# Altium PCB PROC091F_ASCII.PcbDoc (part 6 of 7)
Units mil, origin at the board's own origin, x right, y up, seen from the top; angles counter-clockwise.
Board outline 3590.95 x 906.17 mil, 8 copper layers (Top Layer, GND1, Sig1, PWR1, PWR2, Sig2, GND2, Bottom Layer), stack 63.146 mil thick; 420 components, 316 nets, 1432 pads, 774 vias.
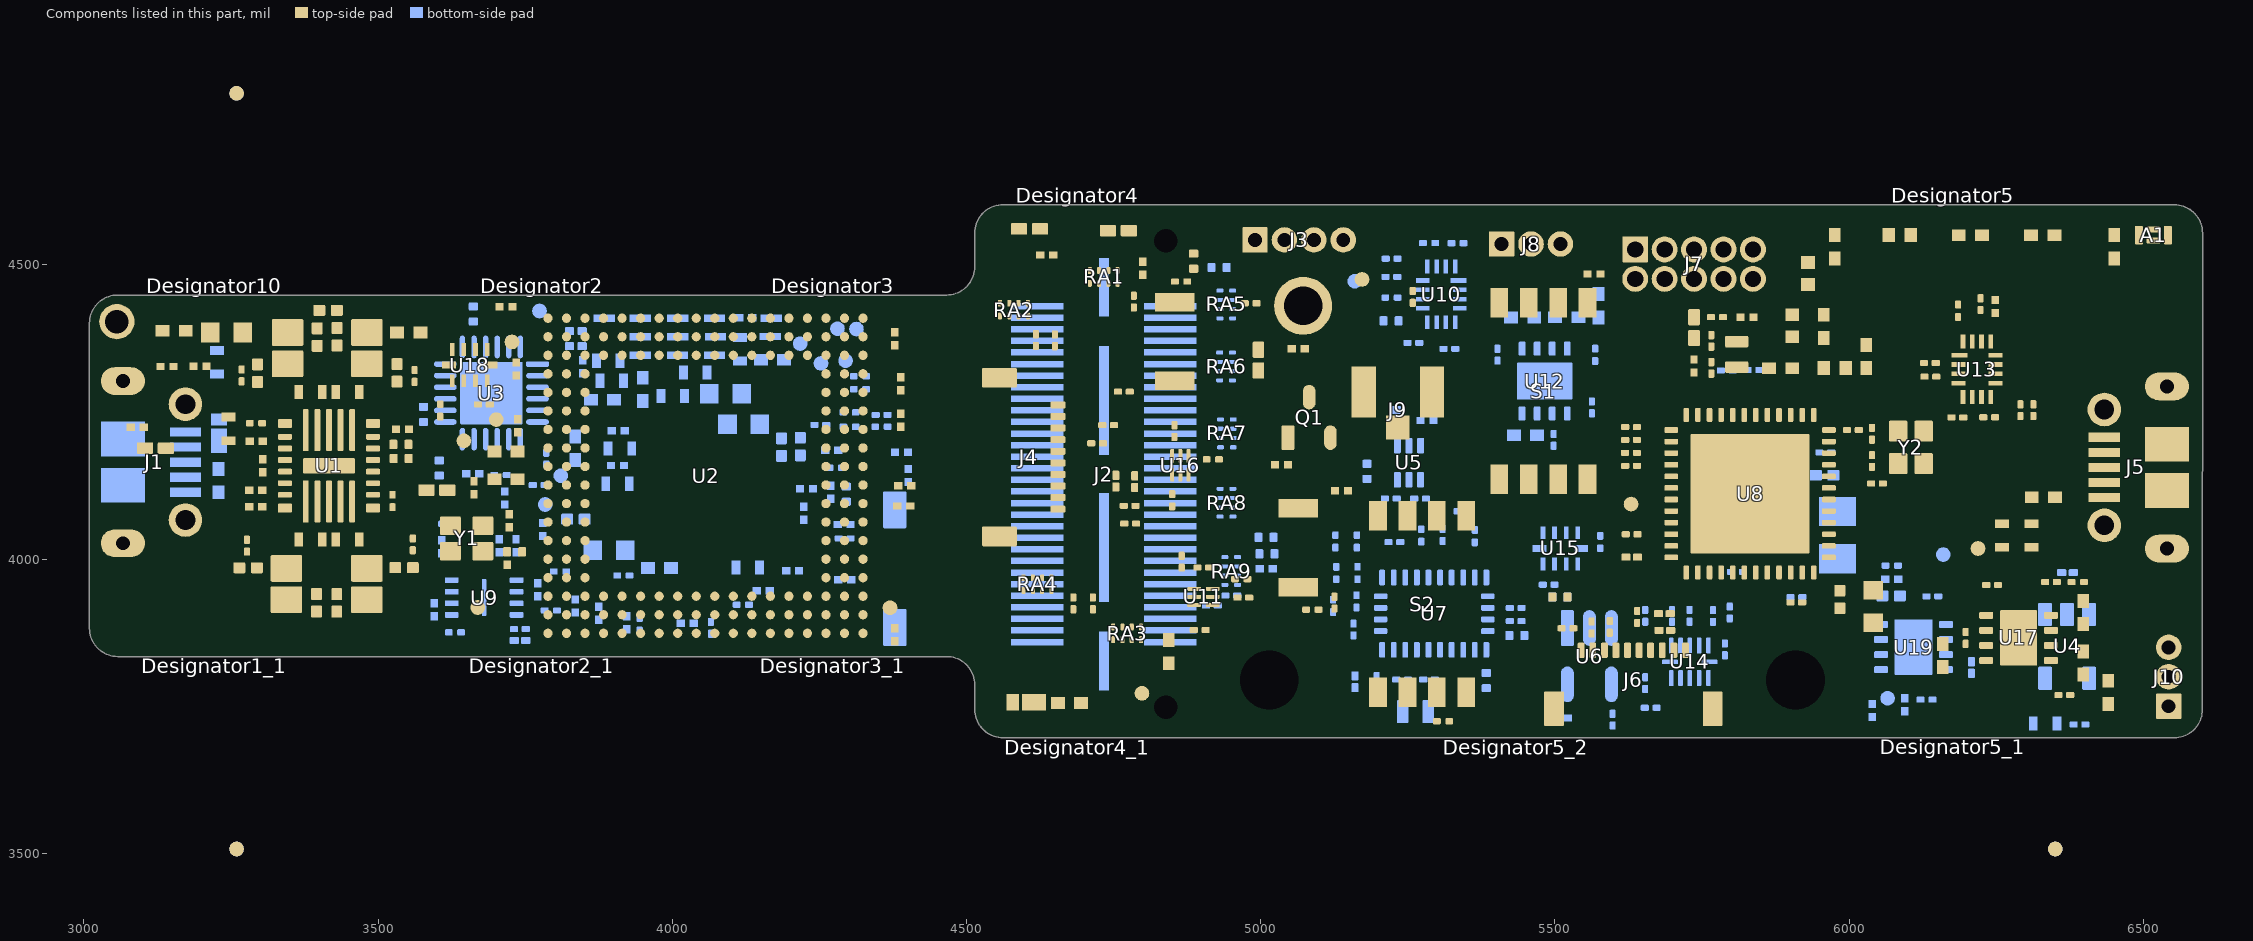
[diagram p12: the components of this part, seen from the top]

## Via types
v1: diameter 18, hole 8, Top Layer to Bottom Layer, tented both sides, 737 vias
v2: diameter 19.68, hole 7.87, Top Layer to Bottom Layer, tented both sides, 36 vias
v3: diameter 17, hole 8, Top Layer to Bottom Layer, tented both sides, 1 vias

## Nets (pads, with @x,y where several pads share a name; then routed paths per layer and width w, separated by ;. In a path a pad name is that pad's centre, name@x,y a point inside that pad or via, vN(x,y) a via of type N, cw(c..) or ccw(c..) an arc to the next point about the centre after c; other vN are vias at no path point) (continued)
pads on no net: A1.2-3 A1.5-6 Designator1. Designator1_1. Designator2. Designator2_1. Designator3. Designator3_1. Designator4. Designator4_1. Designator5. Designator5_1. Designator5_2. Designator6. Designator7. Designator8. Designator10. Designator22_1. Designator23. FID1.1 FID2.1 FID3.1 FID4.1 FID5.1 FID6.1 J1.4 J2.1 J2.3 J2.4 J2.5 J2.6 J2.7 J2.9 J2.MH1 J2.MH2 J4.4 J5.2 J5.3 J5.4 J6.4 J9.2@5173.9,4283.6 J9.3@5292.01,4283.6 RA2.1 RA2.8 RA5.4 RA5.5 S2.4 S2.5 U1. U2.A3 U2.A4 U2.B3 U2.B4 U2.B5 U2.C3 U2.C4 U2.C5 U3.10 U3.11 U3.14 U3.15 U3.16 U3.18 U3.19 U3.21 U3.22 U3.23 U3.24 U7.1 U7.7 U7.8 U7.12 U7.13 U7.15 U7.16 U7.18 U7.21 U7.22 U7.23 U7.24 U8.5 U8.6 U8.9 U8.10 U8.12 U8.18 U8.19 U8.20 U8.28 U8.32 U8.36 U8.37 U8.38 U8.39 U8.40 U8.41 U8.42 U8.43 U12.9@5457.58,4302.51 U12.9@5507.58,4302.51 U17.9@6287.97,3841 U17.9@6287.97,3891 U19.9@6109.37,3825.66 U19.9@6109.37,3875.27

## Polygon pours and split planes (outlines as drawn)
RE on Top Layer "Top Layer-RE" (solid, remove dead copper, pour order 493): 6540.72,4398.89 6564.34,4398.89 6564.34,4587.86 6540.72,4587.86
5V_IN_B on Top Layer "Top Layer-5V_IN_B" (solid, remove dead copper, pour order 491): 6197,4124 6206,4133 6276,4133 6318,4133 6325,4126 6325,4051 6321,4047 6205,4047 6197,4055
USB_5V_B on Top Layer "Top Layer-USB_5V_B" (solid, remove dead copper, pour order 489): 6338,4138.4 6378.89,4138.4 6395.42,4121.87 6402.92,4114.37 6470,4114.37 6476,4108.37 6476,4096.37 6471,4091.37 6338,4091.37 6338,4113.37
no net on Top Layer "Top Layer-No Net" (solid, remove dead copper, pour order 477): 6335,4190
GND on Top Layer " " (solid, remove dead copper, pour order 428): 6462.4,4602.09 6462.4,4476 6094.58,4476 6094.58,4239.36 5840,4239.36 5840,4602.01
GND on Top Layer " " (solid, remove dead copper, pour order 495): 6117.79,4247.89 6117.79,4457 6461.9,4457 6461.9,4318.4 6592,4318.4 6592,3727 6558.63,3693.63 6491,3693.63 4391.1,3693.98 4391.1,4599.81 5818.71,4599.81 5818.71,4287.56 5894.15,4212.11 6082.01,4212.11
GND on Top Layer " " (solid, remove dead copper, pour order 465): 3261.1,4211.1 3261.1,4188.61 3268.49,4181.22 3268.49,4153.29 3150.01,4153.29 3125.63,4177.67 3125.63,4270.32 3146.11,4290.8 3191.47,4290.8 3203.02,4279.24 3203.02,4230.58 3222.51,4211.1
PMICVIO_3V3 on Top Layer " " (solid, remove dead copper, pour order 463): 3143.65,4360.8 3179.4,4360.8 3193.27,4346.93 3193.27,4314.78 3144.6,4314.78 3143.39,4315.99
PMICOUT_3V3 on Top Layer " " (solid, remove dead copper, pour order 461): 4333.76,4153.15 4380.42,4153.15 4392.49,4141.09 4392.49,4117.8 4344.94,4117.8 4327.78,4134.97 4327.78,4146.94 4333.32,4152.48
GND on Top Layer " " (solid, remove dead copper, pour order 446): 4191,4208.15 4106.33,4292.82 3921,4292.82 3921,4016 4191,4016
GND on Top Layer " " (solid, remove dead copper, pour order 430): 3400.13,4047.5 3434.09,4047.5 3435.21,4046.38 3435.21,4007.29 3442,4000.5 3442,3933.2 3386,3933.2 3386,3994.7 3399,4007.7 3399.01,4045.26
GND on Top Layer " " (solid, remove dead copper, pour order 166): 3388.3,4371 3388.3,4316.69 3398.15,4306.84 3398.15,4268.85 3434.85,4269.05 3434.85,4310.34 3441,4316.49 3441,4371
GND on Top Layer " " (solid, remove dead copper, pour order 420): 5383.62,4493.86 5529.19,4493.86 5539.3,4483.75 5539.3,4470.64 5524.82,4456.16 5524.82,4413.01 5517.99,4406.18 5384.16,4406.18 5383.88,4405.9
PMICOUT_3V3 on Top Layer " " (solid, remove dead copper, pour order 396): 3578.7,4436.4 3583.4,4431.7 3583.4,4424.1 3588.9,4418.6 3588.9,4371.27 3557.7,4371.27 3557.7,4405 3541.7,4421 3541.7,4433.07 3545.03,4436.4
PMIC_1V2_FILTERED on Top Layer " " (solid, remove dead copper, pour order 376): 3100.9,4430.37 3096,4425.47 3096,4368.8 3102.63,4361.9 3134.6,4361.9 3149.8,4377.1 3149.8,4430.37
AR_1P2 on Top Layer " " (solid, remove dead copper, pour order 370): 3160.7,4373.3 3191.2,4373.3 3196.93,4367.57 3234.2,4367.57 3234.2,4428 3160.7,4428
PMIC_1V2 on Top Layer "Bottom Layer-PMIC_1V2" (solid, pour order 334): 3406.3,4384 3406.3,4410 3409.8,4413.4 3409.8,4433.17 3252.6,4433.16 3252.6,4361.52 3382,4361.52 3382,4375.99 3390.01,4384
PMIC_1V8 on Top Layer "Bottom Layer-PMIC_1V8" (solid, pour order 338): 3405.2,3921 3372,3921 3372,3952.1 3314,3952.1 3314,3863.25 3405.2,3863.25
5V_IN on Top Layer "Bottom Layer-5V_IN 2" (solid, pour order 346): 3332.61,4303.52 3332.61,4262.52 3372.61,4262.52 3374.61,4264.52 3374.61,4300.52 3371.61,4303.52
PMIC_3V3 on Top Layer "Bottom Layer-PMIC_3V3" (solid, pour order 336): 3539.58,4362.4 3545,4367.82 3545,4380.81 3545,4400.1 3537.2,4407.9 3420,4407.9 3420,4362.4
PMIC_1V0 on Top Layer "Bottom Layer-PMIC_1V0 1" (solid, pour order 340): 3456.41,3953.57 3456.41,3921 3420.5,3921 3420.5,3861.73 3569.79,3861.73 3569.79,3953.57
5V_IN on Top Layer "Bottom Layer-5V_IN 3" (solid, pour order 344): 3332.61,4053.02 3332.61,4012.02 3372.61,4012.02 3374.61,4014.02 3374.61,4050.02 3371.61,4053.02
5V_IN on Top Layer "Bottom Layer-5V_IN 1" (solid, pour order 352): 3500.61,4264.02 3500.61,4305.02 3460.61,4305.02 3458.61,4303.02 3458.61,4267.02 3461.61,4264.02
5V_IN on Top Layer "Bottom Layer-5V_IN 4" (solid, pour order 342): 3500.61,4013.52 3500.61,4054.52 3460.61,4054.52 3458.61,4052.52 3458.61,4016.52 3461.61,4013.52
5V_IN on Top Layer "Top Layer-5V_IN" (solid, pour order 368): 3203.3,4295.75 3209.51,4289.54 3209.51,4241.99 3217.3,4234.2 3221.47,4230.03 3264.77,4230.03 3264.77,4249.23 3264.77,4343.3 3203.3,4343.3
PMICOUT_3V3 on Top Layer "TOP-PMICOUT_3V3" (solid, remove dead copper, pour order 194): 4858.29,3846.65 4858.29,3928.41 4858.29,3946.33 4808.29,3996.33 4773.82,3996.33 4767,3989.51 4767,3934.57 4808.29,3893.28 4808.29,3853.17 4814.8,3846.65
5V_IN on Top Layer "TOP-5V_IN 1" (solid, pour order 184): 4527.77,3777.41 4588.97,3777.41 4588.97,3712.81 4527.77,3712.81
NetD2_2 on Top Layer "TOP-NetD2_2" (solid, pour order 180): 4603.5,3789.43 4657.11,3789.43 4668.11,3778.43 4668.11,3724.76 4662.83,3719.49 4610.48,3719.49 4603.5,3726.47
no net on Top Layer "TOP-No Net 2" (solid, pour order 332): 6159.44,4021.48
VCC_BA_3V3 on Top Layer "TOP-VCC_BA_3V3" (solid, pour order 186): 4830.39,3829.83 4860.96,3829.83 4860.96,3775.05 4859.25,3773.34 4827.36,3773.34 4814.82,3785.87 4814.82,3822.44 4822.21,3829.83
5V_IN_SW on Top Layer "TOP-5V_IN_SW" (solid, pour order 182): 4687.48,3786.45 4727.09,3786.45 4741.77,3771.77 4741.77,3725.03 4724.97,3708.22 4682.94,3708.22 4682.94,3781.58
no net on Top Layer "TOP-No Net" (solid, pour order 178): 6163.15,4205.41
RE on Bottom Layer "Bottom Layer-RE" (solid, remove dead copper, pour order 499): 6564.31,4399 6540.69,4399 6540.69,4587.98 6564.31,4587.98
GND on Bottom Layer " " (solid, remove dead copper, pour order 483): 6460,4317.9 6593,4317.9 6593,3722 6567.2,3696.2 6403.68,3696.2 4390.55,3696.54 4390.55,4602.37 6460,4602.37
PMIC_1V0 on Bottom Layer "Bottom Layer-PMIC_1V0" (solid, remove dead copper, pour order 208): 4092.38,4270.62 4099,4264 4117.89,4264 4130.35,4251.54 4130.35,4214.97 4133.62,4211.53 4157.89,4211.53 4176.45,4193.57 4223.58,4193.57 4229.44,4199.44 4229.44,4211.53 4229.44,4293.05 4202.46,4320.04 4092.38,4320.04
GND on Bottom Layer " " (solid, remove dead copper, pour order 475): 3855.4,4434.66 3943.27,4434.66 3943.27,4354.12 3904.58,4354.12 3889.38,4338.92 3889.38,4292.14 3870.15,4292.14 3869.18,4293.11 3869.18,4319.97 3862.3,4326.86 3846.51,4326.86 3845.29,4328.08 3845.29,4344.09 3855.4,4354.2
VCLK_1V8 on Bottom Layer "BOTTOM-VCLK_1V8" (solid, remove dead copper, pour order 234): 3904.31,4184.76 3904.31,4177.71 3900.3,4173.7 3884.7,4173.7 3882.3,4176.1 3882.3,4183.63 3881.18,4184.76 3815,4184.76 3815,4324 3857.74,4324 3857.74,4292.99 3865.06,4285.68 3873.32,4285.68 3876,4282.72 3876,4231 3904.31,4231
GND on Bottom Layer "Bottom Layer-GND" (solid, remove dead copper, pour order 459): 4122.79,4434.87 4123.42,4403.12 4126.97,4399.57 4126.97,4327.5 4076.38,4327.5 4076.41,4434.87
GND on Bottom Layer "Bottom Layer-GND 1" (solid, remove dead copper, pour order 454): 4039.05,4265.4 4039.05,4433.84 4013.12,4433.84 4013.07,4265.4
GND on Bottom Layer "BOTTOM-GND 1" (solid, remove dead copper, pour order 220): 4223.9,4105.7 4227.1,4108.9 4227.1,4200.2 4065.46,4200.2 4065.46,4221.1 4061.14,4225.42 3946.37,4225.42 3946.37,4017.76 3948.37,4015.76 4203.3,4015.76 4203.3,4099.8 4209.2,4105.7
AR_1V8 on Bottom Layer " " (solid, remove dead copper, pour order 212): 3882,4229.79 3928.75,4229.79 3928.75,4280.65 3887.42,4280.65 3887.42,4264.15 3882,4258.74
no net on Bottom Layer " " (solid, remove dead copper, pour order 452): 4514.15,4464.37
GND on Bottom Layer " " (solid, remove dead copper, pour order 444): 3110.02,4464.37 3516.63,4464.37 3524,4457 3524,3995 3572,3947 3571,3946 3571,3834.46 3009.58,3834.46 3007,3837.04 3007,3956.14 3242.4,3956.14 3293,4006.74 3293,4336 3286,4343 3110.02,4343
5V_IN on Bottom Layer " " (solid, remove dead copper, pour order 442): 5372.93,4241.23 5372.93,4218.21 5399.81,4191.33 5443.81,4191.33 5443.81,4218.26 5420.84,4241.23
no net on Bottom Layer " " (solid, remove dead copper, pour order 440): 5395.85,4242.93
PMICOUT_3V3 on Bottom Layer "Bottom Layer-PMICOUT_3V3" (solid, remove dead copper, pour order 434): 4002.93,3945.37 4022.3,3925.99 4022.3,3871.07 4000.71,3849.47 3984.65,3849.47 3972.61,3861.52 3972.61,3890.23 3968.59,3894.25 3912.61,3894.25 3895.73,3911.13 3853.93,3911.13 3842.3,3922.76 3794.48,3922.76 3794.48,3968.8 3849.6,3968.8 3849.6,3945.37
GND on Bottom Layer "TOP-GND 1" (solid, remove dead copper, pour order 432): 3201.16,4249.63 3201.16,4448.76 3021.38,4448.76 3021.38,3991.45 3045.02,3967.81 3228.75,3967.81 3240.08,3979.14 3240.08,4092.57 3213.15,4119.5 3114.15,4119.5 3110.56,4123.1 3110.56,4154.46 3110.56,4243.98 3116.94,4250.83 3141.88,4250.83 3152.4,4240.31 3191.84,4240.31
no net on Bottom Layer " " (solid, remove dead copper, pour order 416): 3587.57,4371.27
no net on Bottom Layer " " (solid, remove dead copper, pour order 398): 3587.57,4371.27
AR_1V8 on Bottom Layer "Bottom Layer-AR_1V8" (solid, pour order 374): 4178,4325.46 4178,4351.06 4242.56,4351.06 4255.37,4338.24 4255.37,4320.81 4205.03,4320.81 4200.37,4325.46
5V_IN on Bottom Layer "Bottom Layer-5V_IN" (solid, remove dead copper, pour order 372): 3207,4317 3207,4299.06 3201.77,4293.83 3201.77,4225.23 3275.77,4225.23 3275.77,4322.2 3212.2,4322.2
NetD1_2 on Bottom Layer "Bottom Layer-NetD1_2" (solid, remove dead copper, pour order 354): 3205.06,4138.73 3205.06,4217.16 3252.84,4217.16 3252.84,4138.73
USB_5V on Bottom Layer "Bottom Layer-USB_5V" (solid, remove dead copper, pour order 326): 3143.37,4122.78 3209.76,4122.78 3213.9,4126.93 3240.58,4126.93 3240.58,4086.12 3208.69,4086.12 3196.02,4098.78 3143.37,4098.78
PMIC_1V8 on Bottom Layer "BOTTOM-PMIC_1V8 1" (solid, remove dead copper, pour order 214): 3872.59,3942.39 3887.8,3957.6 3887.8,3967.64 3887.8,3992.9 3884.12,3996.58 3884.12,4079.43 3838.37,4079.43 3838.37,3998.24 3838.37,3979.64 3838.88,3963.12 3859.61,3942.39
BB_1V8 on Bottom Layer "Bottom Layer-BB_1V8" (solid, remove dead copper, pour order 324): 4129.35,4407.73 4135.08,4402.01 4135.08,4354.75 4127.11,4346.78 4103.27,4346.78 4103.27,4328.02 4162.87,4328.02 4162.87,4434.77 4129.35,4434.77
AR_VOUT_PA on Bottom Layer "Bottom Layer-AR_VOUT_PA" (solid, remove dead copper, pour order 322): 3901.93,4289 3973.82,4289 3973.82,4434.64 3948.08,4434.64 3948.08,4351 3901.93,4351
AR_1P0_RF2 on Bottom Layer "Bottom Layer-AR_1P0_RF2" (solid, remove dead copper, pour order 318): 3963.8,4285.5 3972.6,4294.3 3972.6,4316.74 3979.83,4323.97 3979.83,4434.54 4004.92,4434.54 4004.92,4266.88 4013.78,4258.02 4110.46,4258.02 4110.46,4211.45 3938.58,4211.45 3938.58,4285.5
AR_1P0_RF1 on Bottom Layer "Bottom Layer-AR_1P0_RF1" (solid, remove dead copper, pour order 316): 4078.8,4266.48 4078.8,4328.27 4069.71,4337.42 4069.71,4434.87 4047.32,4434.87 4047.32,4266.48
VCO_1V8 on Bottom Layer "BOTTOM-VCO_1V8" (solid, remove dead copper, pour order 216): 3877.1,4169.4 3879.6,4166.9 3880.7,4166.83 3904,4166.83 3904,4115.29 3858.83,4115.29 3841.37,4132.76 3841.37,4145.76 3834.37,4152.76 3823.37,4152.76 3823.37,4182.24 3872.16,4182.24 3877.1,4177.3
5V_IN_SW on Bottom Layer "BOTTOM-5V_IN_SW" (solid, pour order 314): 6204.14,3845.14 6152,3845.14 6152,3829.3 6184.9,3829.3 6194.46,3819.74 6201.27,3819.74 6214.64,3819.74 6227.76,3806.61 6228.14,3780.46 6259.4,3749.2 6306.1,3749.2 6314,3757.1 6314,3802 6309,3807 6289,3807 6270.12,3807 6265.37,3811.75 6265.37,3844 6261,3848 6207,3848
5V_HD_IN on Bottom Layer "BOTTOM-5V_HD_IN" (solid, pour order 312): 6136.34,3818.2 6186,3818.2 6198,3806.2 6198,3719.23 6186.95,3708.18 6148.42,3708.18 6136.34,3720.26
5V_IN_B on Bottom Layer "BOTTOM-5V_IN_B" (solid, pour order 266): 6150.95,3923.95 6168.05,3906.85 6178,3896.9 6177.89,3880.17 6174.12,3876.4 6145.16,3876.4 6145.15,3856.3 6204.5,3856.3 6224.8,3876.6 6224.8,3983.2 6267,4025.4 6267,4114 6261,4120 6190,4120 6183,4113 6183,4071.4 6147.37,4035.77 6147.37,3927.53 6149.7,3925.2
5V_HD_IN on Bottom Layer "BOTTOM-5V_HD_IN 1" (solid, pour order 264): 4798.68,3865.13 4891.75,3865.13 4895,3861.88 4895,3789.79 4874.5,3789.79 4874.5,3806.35 4853.33,3827.52 4799.46,3827.52 4791.67,3835.3 4791.67,3858.12
no net on Bottom Layer "BOTTOM-No Net 3" (solid, pour order 262): 4918.91,3816.49
no net on Bottom Layer "BOTTOM-No Net 4" (solid, pour order 254): 4983.76,3878.78
no net on Bottom Layer "BOTTOM-No Net" (solid, pour order 252): 4304.65,4371.57
no net on Bottom Layer "BOTTOM-No Net 1" (solid, remove dead copper, pour order 250): 4033.37,4452.75
VIOIN_1V8 on Bottom Layer "BOTTOM-VIOIN_1V8" (solid, remove dead copper, pour order 230): 3990.37,4003.76 4117.79,4003.76 4117.79,3965.76 3990.37,3965.76
AR_1V8 on Bottom Layer "BOTTOM-AR_1V8" (solid, remove dead copper, pour order 210): 3914,4112 3916.2,4109.8 3936.13,4109.8 3936.13,4014.99 3952.88,3998.24 3972.37,3998.24 3972.37,3968.76 3925.86,3968.76 3891.86,4002.75 3891.86,4112
5V_IN_SW on PWR1 "PWR1-5V_IN_SW" (solid, remove dead copper, pour order 380): 6460,4594 5576,4594 5576,4332 5573.19,4333.81 5443.38,4204 5342,4204 5168,4378 4799.73,4378 4635,4213.27 4635,3697.46 4787.37,3697.46 4787.37,4055.46 5593,4055.46 5685.13,4147.6 6063.4,4147.6 6208.37,4002.63 6208.37,3915.48 6208.37,3699.46 6212.37,3695.46 6600.27,3697.49 6600.27,4318.3 6460,4318.3
5V_IN on PWR1 " " (solid, remove dead copper, pour order 424): 4772.01,4379.61 5180.02,4379.61 5339.66,4219 5561.97,4219 5562.03,4602.1 4675.1,4602.1 4525.19,4452.19 4525.19,3711.47 4631,3711.47 4631,4238.6
PMIC_1V2_FILTERED on PWR1 " " (solid, remove dead copper, pour order 414): 3081.05,4368.79 3181.54,4368.79 3220.45,4329.88 3220.45,4278.41 3246.29,4253.3 4220.68,4253.3 4220.68,4082.23 3738.33,4082.23 3738.33,3834.46 4441,3834.46 4441,4479.05 3081.05,4479.05
PMIC_1V0 on PWR1 " " (solid, remove dead copper, pour order 410): 3579.52,3834.32 3706.3,3834.32 3728.18,3856.2 3728.18,3976.65 3735.92,3985.74 3753.02,4002.3 3785.58,4034.86 3816.78,4034.86 3823.42,4028.23 4160.28,4028.23 4217,4084.96 4217,4319.77 3964.71,4319.77 3942.89,4297.89 3709.16,4297.89 3549.35,4138.08 3549.76,4055.03 3427,4055.03 3427,3832.13
PMICVIO_3V3 on PWR1 " " (solid, remove dead copper, pour order 436): 3141.44,4363.71 3183.96,4363.71 3185.46,4362.21 3185.46,4340.46 3180.45,4335.44 3145.7,4335.44 3141.19,4339.96
5V_HD_IN on PWR1 "PWR1-5V_HD_IN" (solid, remove dead copper, pour order 366): 5560.3,4032.46 5616.87,4032.46 5709.3,4124.9 6042.1,4124.9 6200.37,3966.63 6200.37,3911.2 6200.37,3696.46 4809.37,3696.46 4809.37,4032.46
no net on PWR1 "L4 PWR/GND-No Net" (solid, pour order 364): 3990.62,3973.27
GND on Sig1 " " (solid, remove dead copper, pour order 422): 6460,4568 6486,4568 6486,4533 6460,4533 6460,4318.3 6578,4318.3 6578,3696.46 4514.15,3696.46 4514.15,4605.43 6460,4602.79
GND on Sig1 " " (solid, remove dead copper, pour order 457): 3009.58,4448.76 4380.91,4448.76 4380.91,3834.46 3009.58,3834.46
no net on Sig1 "Sig1-No Net" (solid, remove dead copper, pour order 467): 4088.43,4327.31
no net on Sig1 "L3 SIG 1-No Net" (solid, pour order 286): 3904.98,3968.25
GND on GND1 "GND1-GND" (solid, remove dead copper, pour order 358): 6461.95,4318.4 6592,4318.4 6592,3731 6557.46,3696.46 6403.15,3696.46 4522.29,3696.46 4522.29,3843 3009.59,3843 3010,4451.17 4522,4451.17 4522,4602.1 6462.12,4602.1
no net on GND1 "L6 SIG 2-No Net" (solid, pour order 302): 4825.92,3926.28
no net on GND1 "DVDD_21MP_1V8_L08_P-001" (solid, remove dead copper, pour order 300): 3885.7,4256.64
GND on Sig2 " " (solid, remove dead copper, pour order 438): 6460,4318.1 6587.8,4318.1 6587.8,3725.8 6558.46,3696.46 6403.68,3696.46 4514.15,3696.46 4514.15,4602.37 6460,4602.09
GND on Sig2 " " (solid, remove dead copper, pour order 455): 3009.58,3834.46 3009.58,4448.76 3879.97,4448.76 3880.04,4448.69 3880.04,4344.3 3857.77,4322.03 3857.77,4183.05 3837.69,4162.97 3514.11,4162.97 3449.26,4098.12 3449.26,3833.82
GND on Sig2 " " (solid, remove dead copper, pour order 450): 3946,4059 3946,4264 3971,4289 4166.06,4289 4180,4275.06 4180,4011 4161.3,4011 4128.3,3978 4046,3978 4046,4038 4031.47,4052.53 3952.19,4052.53 3952.19,4053.61 3950,4055.8
AR_1V8 on Sig2 " " (solid, remove dead copper, pour order 426): 3873,4353 4232,4353 4232,4303.36 4226.81,4298.16 3937.21,4298.16 3937.21,4036.72 3873,4036.72
PMICOUT_3V3 on Sig2 "Sig2-PMICOUT_3V3" (solid, remove dead copper, pour order 418): 3572.53,3970.25 3572.53,4012.87 3623.66,4064 3653.69,4094.03 3653.69,4152.2 3646.43,4159.46 3526.74,4159.46 3451.99,4084.71 3452,4019.78 3553.65,3918.12 3572.53,3899.24 3626.57,3899.24 3655.68,3870.12 3776.74,3870.12 3856.78,3950.17 3853.77,3950.17 3840.25,3963.68 3675.96,3963.68 3673.49,3961.21 3581.57,3961.21
GND on Sig2 "Sig2-GND" (solid, remove dead copper, pour order 356): 6403.37,3696.46
VCC_BA_3V3 on PWR2 "PWR2-VCC_BA_3V3" (solid, remove dead copper, pour order 487): 6460,4318.1 6590,4318.1 6590,3720.8 6565.66,3696.46 6403.15,3696.46 4514.14,3696.46 4514.15,4602.1 6460,4602.1
5V_IN on PWR2 " " (solid, remove dead copper, pour order 485): 4597,4100 4573.8,4123.2 4462.7,4122.8 4327.06,4122.8 4302,4147.86 4302,4211.85 4271.3,4229.17 3971.19,4229.17 3910.94,4289.43 3739.45,4289.43 3706.1,4256.08 3706.1,4178.63 3652.53,4125.06 3616.89,4125.06 3605.42,4136.53 3605.42,4222.9 3515.65,4312.67 3515.76,4378.01 3515.76,4432.4 3198.19,4432.4 3198.19,3952.63 3864.68,3952.63 3932.69,4020.64 4127.7,4020.64 4153.58,3994.76 4193.24,3994.76 4229.16,3958.84 4262.42,3957.75 4286.21,3957.75 4322,3921.96 4322,3876.09 4353.26,3844.83 4413.43,3844.83 4439.46,3818.81 4453.67,3818.32 4524.36,3818.32 4529.66,3813.02 4529.66,3715.56 4542.09,3703.14 4743.98,3703.14 4743.98,3847.78 4597,3994.76
PMIC_1V8 on PWR2 "PWR2-PMIC_1V8" (solid, remove dead copper, pour order 408): 3465.34,3966.41 3477.2,3978.26 3537.59,3978.27 3549.67,3966.41 3675.7,3966.41 3707.69,3998.39 3770.3,4061 3870.8,4061 3923.48,4008.32 3923.48,3971.82 3784.28,3832.62 3321.9,3832.62 3321.9,3939.88 3413.11,3939.88 3439.64,3966.41
PMICOUT_3V3 on PWR2 " " (solid, remove dead copper, pour order 402): 4579.6,4126.82 4610.8,4095.62 4611.23,4071.6 4610.88,3988.27 4674.1,3925.05 4803.53,3925.05 4803.53,4471.18 3554,4471.18 3533.3,4449.2 3533.3,4323.11 3545.61,4310.8 3545.61,4215 3545.94,4191.06 3601,4136 3647.82,4136 3683.51,4171.69 3683.51,4257.46 3728.27,4302.22 3926.07,4302.22 3988.19,4240.11 4270.16,4240.11 4301.92,4208.35 4301.92,4163.3 4332.23,4133 4415.98,4133 4422.16,4126.82
VIOIN_1V8 on PWR2 "PWR2-VIOIN_1V8" (solid, remove dead copper, pour order 382): 4282.76,3946.1 4220.49,3946.1 4182.83,3983.77 4150.56,3983.77 4124.13,4011.02 3956.82,4011.02 3876.24,3930.44 3806.05,3930.44 3784.21,3908.6 3784.21,3853.04 3800.87,3836.38 4223.5,3836.38 4269.97,3836.6 4310.66,3877.29 4310.66,3918.2
no net on PWR2 " " (solid, remove dead copper, pour order 406): 3419.66,3833.17
VDDS on PWR2 "PWR2-VDDS" (solid, remove dead copper, pour order 404): 5626.72,4273.46 6074.99,4273.46 6074.99,3989.08 6021.81,3935.9 5700.14,3935.9 5626.72,4006.46
no net on Bottom Solder " " (solid): 4167.33,4185.94 4167.33,4145.41 4201.1,4145.41 4201.1,4016.38 4141,4016.38 3946.06,4016.38 3946.06,4226.44 4065.13,4226.39 4065.13,4185.94
no net on Bottom Solder " " (solid): 4441.36,3932.89 4426.11,3932.89 4407,3952 4407,4017.59 4430.02,4040.6 4509.91,4040.6 4517,4033.51 4517,4010.42 4514.12,4007.54 4514.12,3932.89
no net on Bottom Solder " " (solid, remove dead copper): 4514.15,4464.37
no net on Bottom Solder " " (solid): 4524.01,4436.06 4523.99,4070 4416,4070 4416,4149 4423,4156 4423,4272 4391.25,4303.75 4391.25,4436.06
no net on Bottom Solder " " (solid, remove dead copper): 4512,4464.37
no net on Top Paste " " (solid): 4115.99,4281.29 4185.42,4211.86 4185.42,4162.8 4066.99,4162.8 4066.99,4281.29
no net on Top Paste " " (solid): 3923.88,4165.3 3923.88,4283.79 4042.31,4283.79 4042.31,4165.3
no net on Top Paste " " (solid): 4066.88,4023.15 4066.88,4141.65 4185.31,4141.65 4185.31,4023.15
no net on Top Paste " " (solid): 3922.68,4025.44 3922.68,4143.93 4041.11,4143.93 4041.11,4025.44
no net on M1 Board Outline " " (solid, remove dead copper): 3143.52,4361.87
no net on M1 Board Outline " " (solid, remove dead copper): 3145.55,4361.06
no net on Top Overlay (solid, remove dead copper): 6039.68,3802.89
GND on GND2 "GND 3-GND" (solid, remove dead copper, pour order 310): 6592,4318.4 6592,3734 6553.59,3695.59 6407.19,3695.59 5808.37,3696.46 5113.76,3696.46 5113.76,3832.98 5059.11,3887.63 4965.39,3887.63 4911.96,3834.2 4911.96,3696.46 4522.31,3696.46 4522.31,3842.62 3017.74,3842.62 3009.58,3842.62 3009.41,4456.16 4522.77,4456.16 4522.77,4602.1 5954.75,4602.1 6460,4602.1 6460,4318.4
no net on Top Solder " " (solid): 3923.88,4165.3 3923.88,4283.79 4042.31,4283.79 4042.31,4165.3
no net on Top Solder " " (solid): 3922.68,4025.44 3922.68,4143.93 4041.11,4143.93 4041.11,4025.44
no net on Top Solder " " (solid): 4066.88,4023.15 4066.88,4141.65 4185.31,4141.65 4185.31,4023.15
no net on Top Solder " " (solid): 4115.99,4281.29 4185.42,4211.86 4185.42,4162.8 4066.99,4162.8 4066.99,4281.29

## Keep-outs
Keep-Out Layer:
  circle w1: c5014.62,3794.28 r118.11
  circle w1: c5908.96,3794.29 r118.11
  text ".Layer_Name" at 577,-858.49 h60

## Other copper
Top Layer:
  text ".Layer_Name" at 577,-858.49 h60
GND1:
  text ".Layer_Name" at 577,-858.49 h60
Sig1:
  text ".Layer_Name" at 577,-858.49 h60
PWR1:
  text ".Layer_Name" at 577,-858.49 h60
PWR2:
  text ".Layer_Name" at 577,-858.49 h60
Sig2:
  text ".Layer_Name" at 577,-858.49 h60
GND2:
  text ".Layer_Name" at 577,-858.49 h60
Bottom Layer:
  text ".Layer_Name" at 577,-858.49 h60

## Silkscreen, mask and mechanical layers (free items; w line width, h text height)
Top Overlay:
  drawing of 942 lines, arcs and shapes, not listed
  text "ANT" at 6478,4579 h15
  text "GND" at 5114.35,4578.4 h15
  text "3V3" at 4950.98,4577.16 h15
  text "USR_LED" at 4818.7,4574.89 h13
  text "CAN1" at 5291,4570 h15
  text "BT_JTAG_HDR" at 5651.88,4570 h15
  text "GND" at 5437.65,4569.42 h15
  text "CAN_H" at 5553.75,4514 h15 r90
  text "3V3" at 4565.47,4510.99 h15
  text "CAN_L" at 5377,4511.33 h15 r90
  text "SCL" at 5029.42,4491.93 h15
  text "SDA" at 5084.28,4492.38 h15
  text "LED" at 4572.72,4480.79 h15
  text "60PIN" at 5447,4475 h15
  text "60PIN/BT" at 5268.65,4473.69 h15
  text "'.PRJ_Number'" at 6342.3,4375.7 h25
  text "CLK_P" at 5208,4367.94 h15
  text "GND" at 3073.5,4351.94 h15
  text "BT_LED" at 5700.07,4342.76 h15 r90
  text "REV. F" at 6363.8,4337.7 h25
  text "RST_LED" at 4958.17,4278.44 h15 r90
  text "RST_SW" at 4817.5,4253.69 h15
  text "5V_LED" at 3052,4164 h15 r90
  text "USB2" at 6325,4156 h15
  text "USB_LED" at 3577.15,4153.31 h15
  text "'.PRJ_Number'" at 3029.24,4120.74 h25
  text "CAN" at 5189,4116.73 h15 r90
  text "BT_EN" at 5304.77,4112.88 h15 r90
  text "60PIN" at 5260.34,4106.72 h15 r90
  text "REV. F" at 3031.28,4071.44 h25
  text "BT" at 5460,4056 h15 r90
  text "SOP1" at 5596.27,4055.51 h15 r90
  text "LCD_DISP2" at 4703.55,4054.67 h15 r90
  text "SOP0" at 5498.3,4045.43 h15 r90
  text "CP2105" at 5420.83,4014.52 h15 r90
  text "USR_SW" at 4995.68,3986.37 h15 r90
  text "LCD_DISP1" at 5562.98,3934.67 h15
  text "3V3" at 3607.22,3910.87 h15
  text "CAN2" at 6434.2,3903.8 h15
  text "CAN_H" at 6435.3,3856.4 h15
  text "GND" at 6494.2,3778.1 h15 r90
  text "CAN_L" at 6443.5,3713 h15
  text "SPI" at 5110,3712.15 h15
  text "BT_DIS" at 5354.22,3711.85 h15
  text "BT/LCD" at 5195.38,3707.13 h15
  text ".Layer_Name" at 557.88,-855.15 h60
Bottom Overlay:
  lines w6: 3211.17,4086.81 3211.17,4074.59 3224.09,4087.51 3211.87,4087.51 ; 3800.91,4331.51 3809.55,4322.87 3809.55,4341.13 3800.91,4332.49 ; 4344.51,4118.42 4332.29,4118.42 4345.21,4131.33 4345.21,4119.11 ; 4566.51,3859.44 4557.87,3850.8 4557.87,3869.06 4566.51,3860.42 ; 4990.16,4510.8 4981.52,4502.16 4999.78,4502.16 4991.14,4510.8 ; 5184.91,3825.15 5172.69,3825.15 5185.61,3812.24 5185.61,3824.46 ; 5205.33,4193.17 5196.69,4184.53 5196.69,4202.79 5205.33,4194.15 ; 5367.37,4475.76 5376.01,4467.12 5376.01,4485.39 5367.37,4476.74 ; 5452.25,4061.61 5443.61,4052.97 5443.61,4071.24 5452.25,4062.6 ; 5498.49,3885.48 5489.85,3876.84 5489.85,3895.1 5498.49,3886.46 ; 5520.3,4218.07 5511.65,4209.43 5529.92,4209.43 5521.28,4218.07 ; 5761.65,3767.96 5753.01,3759.32 5771.27,3759.32 5762.63,3767.96 ; 6025.34,3813.5 6016.7,3804.86 6016.7,3823.12 6025.34,3814.48 ; 6303,3920 6294.36,3911.36 6294.36,3929.62 6303,3920.98 ; 3593.1,3881.3 3606.02,3868.39 3606.02,3880.61 3605.32,3881.3 3593.1,3881.3
  lines w7.64: 3176.91,3867.53 3235.33,3968.73 3293.76,3867.53 3176.91,3867.53
  text "S/N:" at 6579.7,4509 h40
  text "For evaluation only;" at 6527,4410 h30
  text "not FCC approved for resale." at 6528,4360 h30
  text "GND" at 5087.44,4355.96 h15
  text "OPN:" at 6372.5,4229.5 h40
  text "USB1" at 3155.09,3966.74 h15
  text "S3" at 4283.72,3874.95 h25 r270
  text "SOP2" at 4443.82,3859.98 h15 r270
  text ".Layer_Name" at 577,-858.49 h60
Top Paste:
  text ".Layer_Name" at 577,-858.49 h60
Bottom Paste:
  text ".Layer_Name" at 577,-858.49 h60
Top Solder:
  text ".Layer_Name" at 577,-858.49 h60
  text ".Layer_Name" at 577,-858.49 h60
Bottom Solder:
  text ".Layer_Name" at 577,-858.49 h60
Drill Guide:
  text ".Layer_Name" at 577,-858.49 h60
M1 Board Outline:
  lines w10: 3057.58,3741.94 ccw(c3057.58,3693.94) 3009.58,3693.94 3009.58,3455.37 ccw(c3057.58,3455.37) 3057.58,3407.37 6552.3,3407.37 ccw(c6552.3,3455.37) 6600.3,3455.37 6600.3,3556.22 ccw(c6552.3,3556.22) 6552.3,3604.22 4488.37,3604.22 cw(c4488.37,3652.22) 4440.37,3652.22 4440.37,3693.94 ccw(c4392.37,3693.94) 4392.37,3741.94 3060,3741.94 ; 3057.58,4541.26 cw(c3057.58,4589.26) 3009.58,4589.26 3009.58,4843.47 cw(c3057.58,4843.47) 3057.58,4891.47 6552.3,4891.47 cw(c6552.3,4843.47) 6600.3,4843.47 6600.3,4742.62 cw(c6552.3,4742.62) 6552.3,4694.62 5943,4694.62 cw(c5943,4742.62) 5895,4742.62 5895,4750.95 ccw(c5847,4750.95) 5847,4798.95 4954.37,4798.95 ccw(c4954.37,4750.95) 4906.37,4750.95 4906.37,4742.62 cw(c4858.37,4742.62) 4858.37,4694.62 4488.37,4694.62 ccw(c4488.37,4646.62) 4440.37,4646.62 4440.37,4589.26 cw(c4392.37,4589.26) 4392.37,4541.26 3060,4541.26 ; 4390,3741.94 4390.37,3741.94 ; 4562.14,3696.46 cw(c4562.14,3744.46) 4514.14,3744.46 4514.14,3786.46 ccw(c4466.14,3786.46) 4466.14,3834.46 3057.58,3834.46 cw(c3057.58,3882.46) 3009.58,3882.46 3009.58,4400.76 cw(c3057.58,4400.76) 3057.58,4448.76 4466.15,4448.76 ccw(c4466.15,4496.76) 4514.15,4496.76 4514.15,4554.37 ; 4562.14,3696.51 6552.27,3696.2 ccw(c6552.27,3744.2) 6600.27,3744.2 ; 6600.29,3744.2 6600.53,4554.1 ccw(c6552.53,4554.1) 6552.53,4602.1 4562.15,4602.33 ccw(c4562.15,4554.37) 4514.15,4554.37 ; 4441.36,3957.89 ccw(c4466.36,3957.89) 4466.36,3932.89 4489.12,3932.89 ; 4441.36,3957.89 4441.36,3957.89 ; 4441.36,3957.89 4441.36,3982.54 cw(c4466.36,3982.54) 4466.36,4007.54 ; 4441.37,4316.3 ccw(c4466.37,4316.3) 4466.37,4291.3 4489.13,4291.3 ; 4441.37,4316.3 4441.37,4316.3 ; 4441.37,4316.3 4441.37,4340.95 cw(c4466.37,4340.95) 4466.37,4365.95 ; 4466.36,4007.54 4489.12,4007.54 cw(c4489.12,3982.54) 4514.12,3982.54 4514.12,3957.89 cw(c4489.12,3957.89) 4489.12,3932.89 ; 4466.36,4007.54 4466.36,4007.54 ; 4466.36,4106.32 cw(c4466.36,4131.32) 4441.36,4131.32 4441.36,4160.46 cw(c4466.36,4160.46) 4466.36,4185.46 4489.13,4185.46 ; 4466.36,4106.32 4466.36,4106.32 ; 4466.36,4106.32 4489.13,4106.32 ccw(c4489.13,4131.32) 4514.13,4131.32 4514.13,4160.46 ccw(c4489.13,4160.46) 4489.13,4185.46 ; 4466.37,4365.95 4466.37,4365.95 ; 4466.37,4365.95 4489.13,4365.95 cw(c4489.13,4340.95) 4514.13,4340.95 4514.13,4316.3 cw(c4489.13,4316.3) 4489.13,4291.3 ; 4489.12,3932.89 4489.12,3932.89 ; 4489.13,4185.46 4489.13,4185.46 ; 4489.13,4291.3 4489.13,4291.3 ; 4514.15,4554.37 4514.15,4554.37
  text "M1 Board Outline" at 577,-858.49 h60
M2 Board Dimensions:
  text "X3" at 4261,4078 h60 r90
  text "X3" at 4593,3426 h60
  text "X24" at 7191,3261 h60
  text "X12" at 3883,3246 h60
  text "M2 Board Dimensions" at 577,-858.49 h60
M3 3D STEP Top:
  text ".Layer_Name" at 577,-858.49 h60
M4 3D STEP Bottom:
  text ".Layer_Name" at 577,-858.49 h60
M5 Assembly Top:
  lines w4: 5723,4363 5752,4363
  lines w10: -287.5,-917.17 6312.5,-917.17 ; -287.5,-713.83 6314.5,-713.83 ; -287.5,-510.5 -287.5,-1120.5 3717.5,-1120.5 6314.5,-1120.5 6314.5,-510.5 -287,-510.5 -287,-1120.5 1288.5,-1120.5 ; 2177.5,-1120.5 2177.5,-510.5 ; 3444.5,-713.83 3444.5,-510.5 ; 4284.5,-713.83 4284.5,-510.5 ; 4906.5,-1127 4906.5,-924.17
  text "COMPONENTS MARKED 'DNP' SHOULD NOT BE POPULATED." at -159.85,-299.74 h60
  text "ASSEMBLY VARIANT:" at -160.35,-415.24 h60
  text ".VariantName" at 875.65,-415.24 h60
  text "PCB VIEWED FROM TOP SIDE" at -228.5,-655.67 h60
  text "BOARD #:" at 2248,-655.67 h60
  text ".PRJ_Number" at 2793.5,-655.67 h60
  text "REV:" at 3638,-655.67 h60
  text ".PCB_Rev" at 3929.5,-655.67 h60
  text "SVN REV:" at 4476,-655.67 h60
  text ".VersionControl_RevNumber" at 4982,-655.67 h60
  text ".Layer_Name" at 538.89,-854.26 h60
  text "TID #:" at 2248,-859 h60
  text ".TID" at 2793.5,-859 h60
  text "PLOT NAME =" at -228.5,-1064.34 h60
  text ".plot_File_Name" at 577,-1064.34 h60
  text "GENERATED    :" at 2250,-1064.34 h60
  text ".Print_Date" at 3119.5,-1064.34 h60
  text ".Print_Time" at 3848.5,-1064.34 h60
  text "TEXAS INSTRUMENTS" at 5113,-1064.34 h60
M6 Assembly Bottom:
  lines w10: -288,-714.33 6314,-714.33 ; -286,-917.67 6314,-917.67 ; 1120,-1127.5 1120,-924.67 ; 1742,-714.33 1742,-511 ; 2582,-714.33 2582,-511 ; 3849,-1121 3849,-511 ; 4738,-1121 6313.5,-1121 6313.5,-511 -288,-511 -288,-1121 2309,-1121 6314,-1121 6314,-511
  text "COMPONENTS MARKED 'DNP' SHOULD NOT BE POPULATED." at 6102,-318 h60
  text ".VariantName" at 5058,-434 h60
  text "ASSEMBLY VARIANT:" at 6097,-434 h60
  text ".VersionControl_RevNumber" at 1035.5,-656.17 h60
  text "SVN REV:" at 1541.5,-656.17 h60
  text ".PCB_Rev" at 2088,-656.17 h60
  text "REV:" at 2379.5,-656.17 h60
  text ".PRJ_Number" at 3224,-656.17 h60
  text "BOARD #:" at 3769.5,-656.17 h60
  text "PCB VIEWED FROM BOTTOM SIDE" at 6246,-656.17 h60
  text ".Layer_Name" at 1514.22,-848.89 h60
  text ".TID" at 3224,-859.5 h60
  text "TID #:" at 3769.5,-859.5 h60
  text "TEXAS INSTRUMENTS" at 904.5,-1064.84 h60
  text ".Print_Time" at 2169,-1064.84 h60
  text ".Print_Date" at 2898,-1064.84 h60
  text "GENERATED    :" at 3767.5,-1064.84 h60
  text ".plot_File_Name" at 5440.5,-1064.84 h60
  text "PLOT NAME =" at 6246,-1064.84 h60
M10 Fab Notes:
  drawing of 256 lines, arcs and shapes, not listed
  text "2" at 3215,8061 h70
  text "1" at 739.84,8036.5 h70
  text "3" at 5724.84,8036.5 h70
  text "4" at 8231.51,8036.5 h70
  text "5" at 10730.5,8036.5 h70
  text "6" at 13235.5,8036.5 h70
  text "A" at -416.5,6893.5 h70
  text "A" at 14383.5,6893.5 h70
  text "IMPEDANCE SPECIFICATIONS" at 3734.73,6612.91 h82.24
  text "IMPEDANCE SPECIFICATIONS" at 3734.73,6612.91 h82.24
  text "DESIGN INFORMATION" at 12391.15,6364.21 h60
  text "SL#" at 3623.7,6325.07 h82.24
  text "SL#" at 3623.7,6325.07 h82.24
  text "TYPE" at 4762.75,6325.07 h82.24
  text "TYPE" at 4762.75,6325.07 h82.24
  text "LAYER" at 5963.48,6325.07 h82.24
  text "LAYER" at 5963.48,6325.07 h82.24
  text "TRACEWIDTH(Mils)" at 6650.2,6325.07 h82.24
  text "TRACEWIDTH(Mils)" at 6650.2,6325.07 h82.24
  text "SPACING(Mils)" at 8003.08,6325.07 h82.24
  text "SPACING(Mils)" at 8003.08,6325.07 h82.24
  text "IMPEDANCE(Ohms)" at 9150.36,6325.07 h82.24
  text "IMPEDANCE(Ohms)" at 9150.36,6325.07 h82.24
  text "REF LAYER" at 10416.88,6325.07 h82.24
  text "REF LAYER" at 10416.88,6325.07 h82.24
  text "3.5" at 12769.13,6238.04 h60
  text "MIN. TRACK WIDTH:" at 11746.59,6232.09 h60
  text "MIL" at 12997.59,6232.09 h60
  text "L02,L07" at 10572.95,6143.02 h82.24
  text "L1,L8" at 5993.27,6139.91 h82.24
  text "5.50" at 7141.18,6136.73 h82.24
  text "---" at 8395.37,6136.73 h82.24
  text "50" at 9608.44,6136.73 h82.24
  text "MICROSTRIP" at 3942.46,6127.2 h82.24
  text "01" at 3656.6,6119.46 h82.24
  text "01" at 3656.6,6119.46 h82.24
  text "MIN. CLEARANCE:" at 11746.59,6107.96 h60
  text "3.5" at 12782.83,6107.96 h60
  text "MIL" at 12997.59,6107.96 h60
  text "L07" at 10573.5,6003.62 h82.24
  text "4.5" at 8454.58,6000.21 h82.24
  text "L8" at 5993.27,5995.99 h82.24
  text "EDGE COUPLED MICROSTRIP" at 3943.7,5995.4 h82.24
  text "4.00" at 7141.18,5992.81 h82.24
  text "90" at 9608.44,5992.81 h82.24
  text "02" at 3656.76,5986.5 h82.24
  text "MIN. VIA PAD SIZE:" at 11746.59,5983.83 h60
  text "18" at 12812.84,5983.84 h60
  text "MIL" at 12997.59,5983.83 h60
  text "7" at 8500.11,5863.02 h82.24
  text "L07" at 10572.95,5855.17 h82.24
  text "0.05mm (2MIL)" at 12441.59,5853.93 h60
  text "EDGE COUPLED MICROSTRIP" at 3943.7,5851.99 h82.24
  text "L8" at 5993.27,5852.06 h82.24
  text "4.00" at 7141.18,5848.89 h82.24
  text "100" at 9608.44,5848.89 h82.24
  text "MINIMUM ANNULAR RING" at 11417.36,5845.71 h60
  text "EXTERNAL" at 13149.59,5845.71 h60
  text "03" at 3656.76,5842.58 h82.24
  text "PER" at 11617.36,5735.58 h60
  text "IPC-D-275 CLASS 2 LEVEL C" at 11837.36,5735.58 h60
  text "6.1" at 8500.11,5719.1 h82.24
  text "L03,L06" at 10572.95,5711.25 h82.24
  text "EDGE COUPLED MICROSTRIP" at 3943.7,5708.06 h82.24
  text "L1,L8" at 5993.27,5708.14 h82.24
  text "4.00" at 7141.18,5704.96 h82.24
  text "120" at 9608.44,5704.96 h82.24
  text "04" at 3656.76,5698.66 h82.24
  text "MIL, HOLES" at 13325.59,5635.11 h60
  text "+/-" at 12933.13,5626.52 h60
  text "+/-" at 13787.13,5626.52 h60
  text "REGISTRATION TOLERANCES:" at 11417.36,5625.46 h60
  text "METAL" at 12617.13,5625.46 h60
  text "5" at 13193.33,5625.46 h60
  text "3" at 14026.33,5625.46 h60
  text "MIL" at 14142.59,5625.46 h60
  text "L02/04,L05/07" at 10304.06,5574.08 h82.24
  text "STRIPLINE" at 3939.49,5569.53 h82.24
  text "L3,L6" at 5996.6,5568 h82.24
  text "4.2" at 7141.18,5560.16 h82.24
  text "---" at 8395.37,5560.16 h82.24
  text "50" at 9608.44,5560.16 h82.24
  text "05" at 3656.76,5554.73 h82.24
  text "HOLE SIZE TOLERANCE (UNLESS OTHERWISE SPECIFIED):" at 11417.36,5527.14 h60
  text "+/-" at 13787.13,5524.27 h60
  text "3" at 14026.33,5523.21 h60
  text "MIL" at 14142.59,5523.2 h60
  text "L6" at 5996.6,5424.08 h82.24
  text "EDGE COUPLED STRIPLINE" at 3941.56,5421.85 h82.24
  text "L05/07" at 10461,5422.2 h82.24
  text "6" at 8488.3,5420.35 h82.24
  text "4.00" at 7141.18,5416.24 h82.24
  text "90" at 9608.44,5416.24 h82.24
  text "06" at 3656.76,5410.81 h82.24
  text "MATERIAL:" at 11342.59,5385.56 h60
  text "EDGE COUPLED STRIPLINE" at 3939.49,5284.58 h82.24
  text "L02/04" at 10461,5283.2 h82.24
  text "L3" at 5996.6,5280.16 h82.24
  text "8" at 8488.3,5276.43 h82.24
  text "3.5" at 7141.18,5272.31 h82.24
  text "100" at 9608.44,5272.31 h82.24
  text "07" at 3664.83,5269.22 h82.24
  text "FR-4 High Tg" at 12329.03,5257.03 h60
  text "X" at 12176.59,5254.04 h60
  text "FR-408" at 11763.59,5244.53 h60
  text "OTHER" at 13251.59,5244.53 h60
  text "L1" at 6001.5,5144.87 h82.24
  text "12" at 7149.41,5141.69 h82.24
  text "50" at 9616.67,5141.69 h82.24
  text "10" at 8447.03,5135.03 h82.24
  text "L03" at 10584.7,5133.69 h82.24
  text "COPLANAR" at 3950.69,5132.16 h82.24
  text "08" at 3664.83,5119.09 h82.24
  text "64 MIL (1.62mm) +/-10%" at 12083.69,5101.5 h60
  text "X" at 11963.59,5099.04 h60
  text "THICKNESS:" at 11417.36,5093.27 h60
  text "OTHER" at 13368.59,5093.27 h60
  text "TOLERANCE:" at 11417.36,4954.96 h60
  text "X" at 12265.59,4954.96 h60
  text "ANSI IPC-6012 TYPE 3 CLASS 2" at 12443.6,4954.96 h60
  text "OTHER +/-" at 12443.59,4810.77 h60
  text "BOW & TWIST:" at 11417.36,4665.58 h60
  text "X" at 12265.59,4665.58 h60
  text "ANSI IPC-6012 TYPE 3 CLASS 2" at 12443.6,4665.58 h60
  text "OTHER +/-" at 12443.59,4518.89 h60
  text "B" at -416.5,4513.5 h70
  text "B" at 14383.5,4513.5 h70
  text "DRILLING:" at 11342.59,4388.27 h60
  text "NC_DRILL FILES" at 13103.59,4283.08 h60
  text "REFERENCE:" at 11417.36,4279.14 h60
  text "X" at 12074.59,4279.04 h60
  text "AS SHOWN" at 12252.59,4279.14 h60
  text "X" at 12975.59,4279.14 h60
  text "OTHER" at 13401.59,4136.89 h60
  text "PTH COPPER THICKNESS:" at 11417.03,4133.36 h60
  text "X" at 12556.27,4133.36 h60
  text "20-30 um" at 12684.27,4133.36 h60
  text "BOARD FINISH:" at 11342.59,3985.76 h60
  text "SILKSCREEN:" at 11497.81,3875.64 h60
  text "X" at 12455.59,3875.64 h60
  text "TOP" at 12572.59,3875.64 h60
  text "X" at 12965.59,3875.64 h60
  text "BOTTOM" at 13083.59,3875.64 h60
  text "SILKSCREEN COLOR:" at 11497.81,3720.45 h60
  text "X" at 12454.59,3720.45 h60
  text "WHITE" at 12572.59,3720.45 h60
  text "OTHER" at 13083.59,3720.45 h60
  text "X" at 12585.59,3577 h60
  text "RED" at 12703.59,3577 h60
  text "OTHER" at 13321.59,3577 h60
  text "SOLDER RESIST COLOR:" at 11497.81,3570.13 h60
  text "X" at 12585.59,3422.75 h60
  text "MATTE" at 12703.59,3422.75 h60
  text "SEMI-GLOSS" at 13321.13,3422.11 h60
  text "IMMERSION GOLD (ENIG)" at 12403.59,3249.98 h60
  text "ENEPIG" at 13741.13,3242.75 h60
  text "SURFACE FINISH:" at 11342.59,3241.75 h60
  text "X" at 12225.59,3241.75 h60
  text "IMM. TIN/SILVER OR EQUIV" at 11672.13,3104.44 h60
  text "OTHER" at 13103.59,3100.5 h60
  text "ARRAY/PANEL:" at 11342.59,2945.12 h60
  text "CUT AND TRIM PER M1 BOARD OUTLINE" at 12403.59,2936.9 h60
  text "X" at 12215,2804 h60
  text "N.C. ROUTE" at 12403.59,2800.94 h60
  text "V. SCORE" at 13269.59,2800.94 h60
  text "CERTIFICATION:" at 11342.59,2671.81 h60
  text "MATERIALS AND WORKMANSHIP FOR ALL PCBS" at 12067.59,2671.81 h60
  text "TO MEET OR EXCEED THE REQUIREMENTS OF:" at 12067.59,2577.75 h60
  text "X" at 11705.1,2449.12 h60
  text "ANSI IPC-A-600F CLASS ->" at 11833.09,2449.12 h60
  text "X" at 13481.1,2449.12 h60
  text "2" at 13591.09,2449.12 h60
  text "1" at 13276.09,2447.62 h60
  text "3" at 13945.09,2447.62 h60
  text "X" at 12517.1,2301.43 h60
  text "RoHS" at 12645.09,2301.43 h60
  text "OTHER" at 13289.49,2301.43 h60
  text "PER ORDER" at 13686.55,2301.43 h60
  text "ALL BOARDS MUST MEET OR EXCEED UL94-V0 REQUIREMENTS." at 11370.13,2147.6 h60
  text "C" at -416.5,2138.5 h70
  text "C" at 14383.5,2138.5 h70
  text "PCB MUST BEAR THE UL94V-0 UL REGISTERED MATERIAL ID NUMBER" at 11370.13,2031.54 h60
  text "ADDITIONAL REQUIREMENTS:" at 11342.59,1862.12 h60
  text "MICROSECTION:" at 11417.36,1754.99 h60
  text "YES" at 12323.09,1754.99 h60
  text "REQUIRED" at 13184.59,1610.66 h60
  text "BARE BOARD ELEC. TEST:" at 11417.36,1607.8 h60
  text "NONE" at 12723.09,1607.8 h60
  text "X" at 13066.59,1607.8 h60
  text "PER ORDER" at 13776.59,1607.8 h60
  text "XX MIL VIAS REQUIRE NON-CONDUCTIVE FILL AND PLANARIZE" at 11585.51,1402.85 h59
  text "XX MIL VIAS REQUIRE CONDUCTIVE FILL AND PLANARIZE" at 11593.51,1298.88 h60
  text "X" at 11460.14,1142.4 h60
  text "OUTER XX MIL TRACES REQUIRE 50 OHM SINGLE-ENDED IMPEDANCE" at 11592.52,1135.49 h58
  text "X" at 11462.02,980.86 h60
  text "LAYER 2 & 3 (INNER LAYERS) XX MIL WIDE, XX MIL SPACE / TRACES REQUIRE 100 OHM DIFFERENTIAL IMPEDANCE" at 11584.52,899.78 h60
  text "PROJECT TITLE:" at 11343.5,277.5 h45
  text ".PRJ_Title" at 11393.5,144.17 h70
  text "DESIGNED FOR:" at 11343.5,-23.5 h45
  text ".PRJ_Customer" at 11393.5,-163.5 h70
  text "D" at -416.5,-231.5 h70
  text "D" at 14383.5,-231.5 h70
  text "FILE NAME:" at 11343.5,-323.5 h45
  text ".PCB_File_Name_No_Path" at 11393.5,-443.5 h70
  text "Texas Instruments (TI) and/or its licensors do not warrant the accuracy or completeness of this specification" at 6374,-605.34 h45
  text "ENGINEER:" at 11343.5,-613.5 h45
  text "LAYOUT BY:" at 12848.5,-613.5 h45
  text "or any information contained therein. TI and/or its licensors do not warrant that this design will meet" at 6329.01,-718 h45
  text ".PRJ_Engineer" at 11393.5,-768.49 h70
  text ".PCB_Layout" at 12899,-768.49 h70
  text "the specifications, will be suitable for your application or fit for any particular purpose, or will operate in" at 6329.01,-830.67 h45
  text ".Layer_Name" at 577,-858.49 h60
  text "ALTIUM DESIGNER VERSION:" at 12848.5,-923.5 h45
  text "an implementation. TI and/or its licensors do not warrant that the design is production worthy. You should" at 6329.01,-943.33 h45
  text "completely validate and test your design implementation to confirm the system functionality for your application." at 6374,-1056 h45
  text ".print_Scale" at 11393.5,-1056.83 h70
  text ".Application_BuildNumber" at 12899,-1056.83 h70
  text "1" at 739.84,-1263.5 h70
  text "2" at 3235.5,-1263.5 h70
  text "3" at 5724.84,-1263.5 h70
  text "4" at 8231.51,-1263.5 h70
  text "5" at 10730.5,-1263.5 h70
  text "6" at 13235.5,-1263.5 h70
M11 Gerber Information:
  lines w10: -288.5,-917.67 6311.5,-917.67 ; -288.5,-714.33 6313.5,-714.33 ; -288.5,-511 -288.5,-1121 3716.5,-1121 6313.5,-1121 6313.5,-511 -288,-511 -288,-1121 1287.5,-1121 ; 2176.5,-1121 2176.5,-511 ; 3443.5,-714.33 3443.5,-511 ; 4283.5,-714.33 4283.5,-511 ; 4905.5,-1127.5 4905.5,-924.67
  text "ALL ARTWORK VIEWED FROM TOP SIDE" at -228.5,-655.67 h60
  text "BOARD #:" at 2248,-655.67 h60
  text ".PRJ_Number" at 2793.5,-655.67 h60
  text "REV:" at 3638,-655.67 h60
  text ".PCB_Rev" at 3929.5,-655.67 h60
  text "SVN REV:" at 4476,-655.67 h60
  text ".VersionControl_RevNumber" at 4982,-655.67 h60
  text "LAYER NAME =" at -228.5,-858.49 h60
  text "TID #:" at 2248,-859 h60
  text ".TID" at 2793.5,-859 h60
  text "PLOT NAME =" at -228.5,-1064.34 h60
  text ".plot_File_Name" at 577,-1064.34 h60
  text "GENERATED    :" at 2250,-1064.34 h60
  text ".Print_Date" at 3119.5,-1064.34 h60
  text ".Print_Time" at 3848.5,-1064.34 h60
  text "TEXAS INSTRUMENTS" at 5113,-1064.34 h60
